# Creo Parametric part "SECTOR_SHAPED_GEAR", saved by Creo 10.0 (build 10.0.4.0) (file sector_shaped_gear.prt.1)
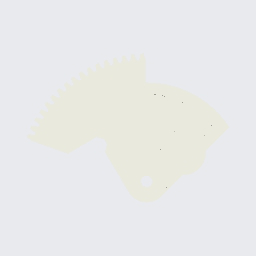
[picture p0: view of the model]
Units: millimeter Kilogram Sec (mmKs); MM, KILOGRAM, SECS

Created from: XX_SOLID_PART_MMKS_NEW_ABS.PRT

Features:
  1. datum plane "RIGHT"
  2. datum plane "TOP"
  3. datum plane "FRONT"
  4. coordinate system
  5. extrusion "Extrude 1"
  6. pattern "Pattern 1"
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
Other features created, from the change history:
  extruded cut "Extrude 2"
  extruded cut "Extrude 2 [2]"
  extruded cut "Extrude 2 [3]"
  extruded cut "Extrude 2 [4]"
  extruded cut "Extrude 2 [5]"
  extruded cut "Extrude 2 [6]"
  extruded cut "Extrude 2 [7]"
  extruded cut "Extrude 2 [8]"
  extruded cut "Extrude 2 [9]"
  extruded cut "Extrude 2 [10]"
  extruded cut "Extrude 2 [11]"
  extruded cut "Extrude 2 [12]"
  extruded cut "Extrude 2 [13]"
  extruded cut "Extrude 2 [14]"
  extruded cut "Extrude 2 [15]"
  extruded cut "Extrude 2 [16]"
  extruded cut "Extrude 2 [17]"
  extruded cut "Extrude 2 [18]"
  extruded cut "Extrude 2 [19]"
  extruded cut "Extrude 2 [20]"
  extruded cut "Extrude 2 [21]"
  extruded cut "Extrude 2 [22]"
  extruded cut "Extrude 2 [23]"
  extruded cut "Extrude 2 [24]"
  extruded cut "Extrude 2 [25]"
  extruded cut "Extrude 2 [26]"
  extruded cut "Extrude 2 [27]"
  extruded cut "Extrude 2 [28]"
  extruded cut "Extrude 2 [29]"
  extruded cut "Extrude 2 [30]"
  extruded cut "Extrude 2 [31]"
  extruded cut "Extrude 2 [32]"
  extruded cut "Extrude 2 [33]"
  extruded cut "Extrude 2 [34]"
  extruded cut "Extrude 2 [35]"
  extruded cut "Extrude 2 [36]"
  extruded cut "Extrude 2 [37]"
  extruded cut "Extrude 2 [38]"
  extruded cut "Extrude 2 [39]"
  extruded cut "Extrude 2 [40]"
  extruded cut "Extrude 2 [41]"
  extruded cut "Extrude 2 [42]"
  extruded cut "Extrude 2 [43]"
  extruded cut "Extrude 2 [44]"
  extruded cut "Extrude 2 [45]"
  extruded cut "Extrude 2 [46]"
  extruded cut "Extrude 2 [47]"
  extruded cut "Extrude 2 [48]"
  extruded cut "Extrude 2 [49]"
  extruded cut "Extrude 2 [50]"
  extruded cut "Extrude 2 [51]"
  extruded cut "Extrude 2 [52]"
  extruded cut "Extrude 2 [53]"
  extruded cut "Extrude 2 [54]"
  extruded cut "Extrude 2 [55]"
  extruded cut "Extrude 2 [56]"
  extruded cut "Extrude 2 [57]"
  extruded cut "Extrude 2 [58]"
  extruded cut "Extrude 2 [59]"
  extruded cut "Extrude 2 [60]"
  extruded cut "Extrude 2 [61]"
  extruded cut "Extrude 2 [62]"
  extruded cut "Extrude 2 [63]"
  extruded cut "Extrude 2 [64]"
  extruded cut "Extrude 2 [65]"
  extruded cut "Extrude 2 [66]"
  extruded cut "Extrude 2 [67]"
  extruded cut "Extrude 2 [68]"
  extruded cut "Extrude 2 [69]"
  extruded cut "Extrude 2 [70]"
  extruded cut "Extrude 2 [71]"
  extruded cut "Extrude 2 [72]"
  extruded cut "Extrude 2 [73]"
  extruded cut "Extrude 2 [74]"
  extruded cut "Extrude 2 [75]"
  extruded cut "Extrude 2 [76]"
  extruded cut "Extrude 2 [77]"
  extruded cut "Extrude 2 [78]"
  extruded cut "Extrude 2 [79]"
  extruded cut "Extrude 2 [80]"
  extruded cut "Extrude 2 [81]"
  extruded cut "Extrude 2 [82]"
  extruded cut "Extrude 2 [83]"
  extruded cut "Extrude 2 [84]"
  extruded cut "Extrude 2 [85]"
  extruded cut "Extrude 2 [86]"
  extruded cut "Extrude 3" (3 times)
  extruded cut "Extrude 4" (2 times)
  chamfer "Chamfer 1" (2 times)
  extrusion "Extrude 5"
  extrusion "Extrude 6"
  extruded cut "Extrude 7"
  extruded cut "Extrude 8"
  extrusion "Extrude 9"

Surfaces: 60 plane, 42 cylinder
